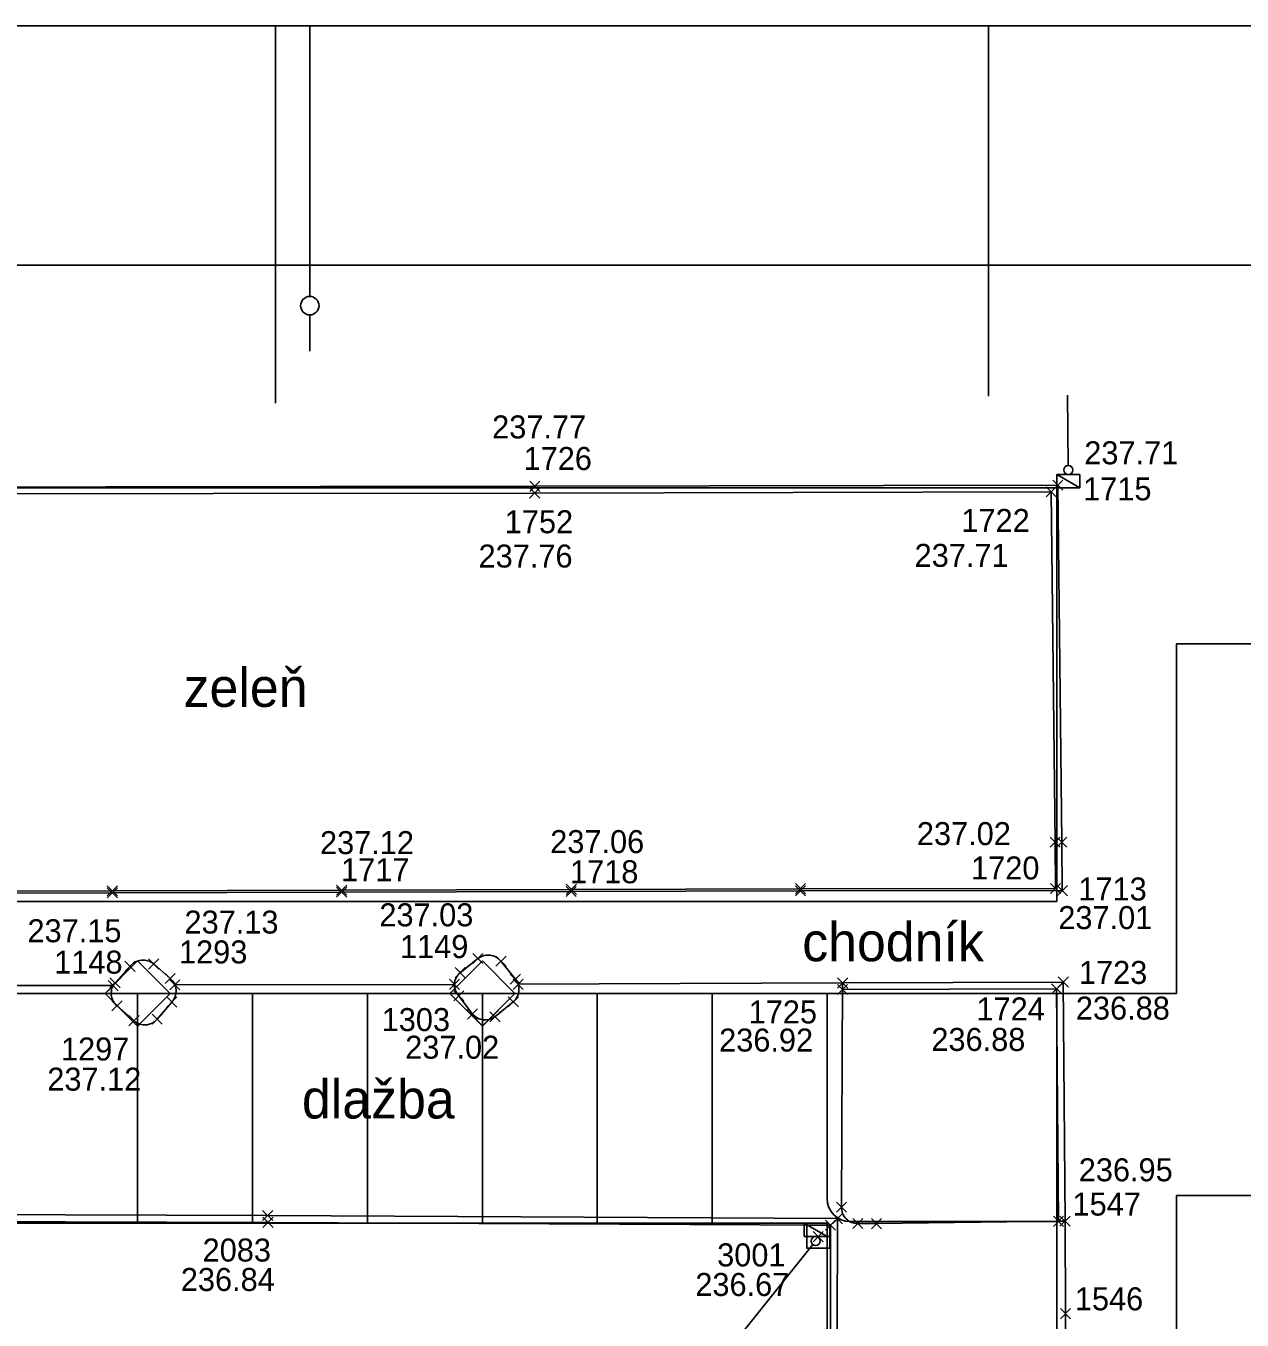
# Model space of a CAD drawing. Extents: x -264165 to -263733, y -1242319 to -1242245.
# Drawn here: x -263824.5 to -263798.04, y -1242273.09 to -1242244.94 of the extents above; entities that cross this region are included whole.
import ezdxf

# ---------------------------------------------------------------- set-up
doc = ezdxf.new("R2010")
doc.units = 0
for name, color, linetype in [('KFA_BOD_CISLO', 7, 'Continuous'), ('KFA_BOD_SYMBOL', 7, 'Continuous'), ('KFA_BOD_VYSKA', 7, 'Continuous'), ('KFA_SO_20-2_OBRUBNIKY_DOLNA_HRANA', 7, 'Continuous'), ('KFA_SO_20-2_OBRUBNIKY_HORNA_HRANA', 7, 'Continuous'), ('KFA_UV_BOD_CISLO', 7, 'Continuous'), ('KFA_UV_BOD_SYMBOL', 7, 'Continuous'), ('KFA_UV_BOD_VYSKA', 7, 'Continuous'), ('POPIS', 7, 'Continuous'), ('PROJEKT_OBRUBNIKY_KOMUNIKACIE', 7, 'Continuous'), ('PROJEKT_TDZ_VODOROVNE', 7, 'Continuous'), ('RAM_NA_TLAC_1-250', 7, 'Continuous'), ('SITUACIA_DSP_2D', 7, 'Continuous'), ('ULICNA_VPUST_POKLOP', 7, 'Continuous')]:
    doc.layers.add(name, color=color, linetype=linetype)

msp = doc.modelspace()

# ---------------------------------------------------------------- linework, layer by layer
at = {"layer": 'KFA_BOD_SYMBOL'}
for p, q in [((-263813.54, -1242255.208), (-263813.318, -1242254.988)), ((-263813.318, -1242255.208), (-263813.54, -1242254.988)), ((-263813.539, -1242255.062), (-263813.318, -1242254.84)), ((-263813.318, -1242255.062), (-263813.539, -1242254.84)), ((-263802.302, -1242255.184), (-263802.081, -1242254.964)), ((-263802.081, -1242255.184), (-263802.302, -1242254.964)), ((-263802.16, -1242255.036), (-263801.938, -1242254.816)), ((-263801.938, -1242255.036), (-263802.16, -1242254.816)), ((-263802.217, -1242262.803), (-263801.996, -1242262.583)), ((-263801.996, -1242262.803), (-263802.217, -1242262.583)), ((-263802.073, -1242262.803), (-263801.851, -1242262.583)), ((-263801.851, -1242262.803), (-263802.073, -1242262.583)), ((-263822.729, -1242263.865), (-263822.508, -1242263.644)), ((-263822.508, -1242263.865), (-263822.729, -1242263.644)), ((-263822.728, -1242263.906), (-263822.507, -1242263.684)), ((-263822.507, -1242263.906), (-263822.728, -1242263.684)), ((-263817.742, -1242263.849), (-263817.52, -1242263.627)), ((-263817.52, -1242263.849), (-263817.742, -1242263.627)), ((-263817.74, -1242263.894), (-263817.519, -1242263.674)), ((-263817.519, -1242263.894), (-263817.74, -1242263.674)), ((-263812.745, -1242263.877), (-263812.524, -1242263.657)), ((-263812.524, -1242263.877), (-263812.745, -1242263.657)), ((-263812.743, -1242263.832), (-263812.522, -1242263.61)), ((-263812.522, -1242263.832), (-263812.743, -1242263.61)), ((-263807.758, -1242263.818), (-263807.536, -1242263.596)), ((-263807.536, -1242263.818), (-263807.758, -1242263.596)), ((-263807.756, -1242263.865), (-263807.535, -1242263.644)), ((-263807.535, -1242263.865), (-263807.756, -1242263.644)), ((-263802.209, -1242263.812), (-263801.987, -1242263.592)), ((-263801.987, -1242263.812), (-263802.209, -1242263.592)), ((-263802.062, -1242263.859), (-263801.841, -1242263.637)), ((-263801.841, -1242263.859), (-263802.062, -1242263.637)), ((-263814.777, -1242265.336), (-263814.556, -1242265.115)), ((-263814.556, -1242265.336), (-263814.777, -1242265.115)), ((-263814.274, -1242265.393), (-263814.052, -1242265.171)), ((-263814.052, -1242265.393), (-263814.274, -1242265.171)), ((-263822.345, -1242265.505), (-263822.123, -1242265.285)), ((-263822.123, -1242265.505), (-263822.345, -1242265.285)), ((-263821.829, -1242265.454), (-263821.608, -1242265.232)), ((-263821.608, -1242265.454), (-263821.829, -1242265.232)), ((-263815.163, -1242265.646), (-263814.942, -1242265.424)), ((-263814.942, -1242265.646), (-263815.163, -1242265.424)), ((-263822.71, -1242265.926), (-263822.489, -1242265.704)), ((-263822.489, -1242265.926), (-263822.71, -1242265.704)), ((-263822.67, -1242265.866), (-263822.448, -1242265.644)), ((-263822.448, -1242265.866), (-263822.67, -1242265.644)), ((-263821.47, -1242265.772), (-263821.25, -1242265.552)), ((-263821.25, -1242265.772), (-263821.47, -1242265.552)), ((-263821.368, -1242265.91), (-263821.147, -1242265.69)), ((-263821.147, -1242265.91), (-263821.368, -1242265.69)), ((-263815.285, -1242265.897), (-263815.064, -1242265.677)), ((-263815.064, -1242265.897), (-263815.285, -1242265.677)), ((-263813.96, -1242265.786), (-263813.739, -1242265.566)), ((-263813.739, -1242265.786), (-263813.96, -1242265.566)), ((-263813.9, -1242265.896), (-263813.679, -1242265.674)), ((-263813.679, -1242265.896), (-263813.9, -1242265.674)), ((-263806.84, -1242265.867), (-263806.619, -1242265.646)), ((-263806.619, -1242265.867), (-263806.84, -1242265.646)), ((-263802.041, -1242265.847), (-263801.819, -1242265.627)), ((-263801.819, -1242265.847), (-263802.041, -1242265.627)), ((-263815.191, -1242266.149), (-263814.97, -1242265.927)), ((-263814.97, -1242266.149), (-263815.191, -1242265.927)), ((-263806.842, -1242266.009), (-263806.621, -1242265.789)), ((-263806.621, -1242266.009), (-263806.842, -1242265.789)), ((-263802.185, -1242265.995), (-263801.964, -1242265.775)), ((-263801.964, -1242265.995), (-263802.185, -1242265.775)), ((-263822.627, -1242266.363), (-263822.405, -1242266.143)), ((-263822.405, -1242266.363), (-263822.627, -1242266.143)), ((-263821.433, -1242266.284), (-263821.212, -1242266.062)), ((-263821.212, -1242266.284), (-263821.433, -1242266.062)), ((-263814.007, -1242266.279), (-263813.785, -1242266.059)), ((-263813.785, -1242266.279), (-263814.007, -1242266.059)), ((-263822.258, -1242266.69), (-263822.036, -1242266.468)), ((-263822.036, -1242266.69), (-263822.258, -1242266.468)), ((-263821.754, -1242266.654), (-263821.533, -1242266.434)), ((-263821.533, -1242266.654), (-263821.754, -1242266.434)), ((-263814.894, -1242266.543), (-263814.672, -1242266.323)), ((-263814.672, -1242266.543), (-263814.894, -1242266.323)), ((-263814.405, -1242266.603), (-263814.183, -1242266.382)), ((-263814.183, -1242266.603), (-263814.405, -1242266.382)), ((-263806.866, -1242270.747), (-263806.644, -1242270.525)), ((-263806.644, -1242270.747), (-263806.866, -1242270.525)), ((-263819.35, -1242270.927), (-263819.128, -1242270.707)), ((-263819.128, -1242270.927), (-263819.35, -1242270.707)), ((-263806.951, -1242270.995), (-263806.73, -1242270.774)), ((-263806.73, -1242270.995), (-263806.951, -1242270.774)), ((-263819.344, -1242271.076), (-263819.122, -1242270.855)), ((-263819.122, -1242271.076), (-263819.344, -1242270.855)), ((-263807.105, -1242271.137), (-263806.883, -1242270.916)), ((-263806.883, -1242271.137), (-263807.105, -1242270.916)), ((-263806.508, -1242271.1), (-263806.287, -1242270.88)), ((-263806.287, -1242271.1), (-263806.508, -1242270.88)), ((-263806.105, -1242271.103), (-263805.883, -1242270.883)), ((-263805.883, -1242271.103), (-263806.105, -1242270.883)), ((-263802.145, -1242271.052), (-263801.924, -1242270.832)), ((-263801.924, -1242271.052), (-263802.145, -1242270.832)), ((-263802.001, -1242271.049), (-263801.78, -1242270.829)), ((-263801.78, -1242271.049), (-263802.001, -1242270.829)), ((-263801.992, -1242273.062), (-263801.771, -1242272.84)), ((-263801.771, -1242273.062), (-263801.992, -1242272.84))]:
    msp.add_line(p, q, dxfattribs=at)
at = {"layer": 'KFA_SO_20-2_OBRUBNIKY_DOLNA_HRANA'}
for p, q in [((-263819.239, -1242270.817), (-263806.84, -1242270.884)), ((-263819.233, -1242270.965), (-263806.994, -1242271.026))]:
    msp.add_line(p, q, dxfattribs=at)
for points in [[(-263870.268, -1242270.778), (-263860.244, -1242270.766), (-263850.281, -1242270.766), (-263840.271, -1242270.772), (-263830.256, -1242270.782), (-263819.239, -1242270.817)], [(-263870.27, -1242270.923), (-263860.247, -1242270.914), (-263850.285, -1242270.903), (-263840.274, -1242270.913), (-263830.254, -1242270.929), (-263819.233, -1242270.965)], [(-263806.994, -1242271.026), (-263807.002, -1242275.743), (-263807.011, -1242281.745), (-263807.02, -1242285.741), (-263807.029, -1242285.754), (-263811.073, -1242288.555), (-263815.133, -1242291.369), (-263816.759, -1242292.501), (-263817.492, -1242292.982)], [(-263806.84, -1242270.884), (-263806.855, -1242275.745), (-263806.866, -1242281.754), (-263806.878, -1242285.825), (-263810.985, -1242288.673), (-263815.032, -1242291.478), (-263816.678, -1242292.619), (-263817.431, -1242293.129)]]:
    msp.add_lwpolyline(points, dxfattribs=at)
at = {"layer": 'KFA_SO_20-2_OBRUBNIKY_HORNA_HRANA'}
for p, q in [((-263801.962, -1242262.693), (-263802.049, -1242254.926)), ((-263802.106, -1242262.693), (-263802.192, -1242255.074)), ((-263802.098, -1242263.702), (-263802.106, -1242262.693)), ((-263801.952, -1242263.748), (-263801.962, -1242262.693)), ((-263826.616, -1242263.765), (-263822.618, -1242263.754)), ((-263822.618, -1242263.754), (-263817.631, -1242263.738)), ((-263817.631, -1242263.738), (-263812.633, -1242263.721)), ((-263817.629, -1242263.784), (-263812.634, -1242263.767)), ((-263812.634, -1242263.767), (-263807.645, -1242263.754)), ((-263812.633, -1242263.721), (-263807.647, -1242263.707)), ((-263807.647, -1242263.707), (-263802.098, -1242263.702)), ((-263807.645, -1242263.754), (-263801.952, -1242263.748)), ((-263826.618, -1242263.814), (-263822.617, -1242263.795)), ((-263822.617, -1242263.795), (-263817.629, -1242263.784)), ((-263822.559, -1242265.755), (-263822.234, -1242265.395)), ((-263821.719, -1242265.343), (-263821.36, -1242265.662)), ((-263814.666, -1242265.225), (-263815.052, -1242265.535)), ((-263814.163, -1242265.282), (-263813.85, -1242265.676)), ((-263801.93, -1242265.737), (-263806.73, -1242265.756)), ((-263801.93, -1242265.737), (-263801.89, -1242270.939)), ((-263822.6, -1242265.815), (-263828.894, -1242265.814)), ((-263815.175, -1242265.787), (-263821.258, -1242265.8)), ((-263806.73, -1242265.756), (-263813.79, -1242265.785)), ((-263806.755, -1242270.636), (-263806.73, -1242265.756)), ((-263802.074, -1242265.885), (-263806.731, -1242265.899)), ((-263802.035, -1242270.942), (-263802.074, -1242265.885)), ((-263822.147, -1242266.579), (-263822.516, -1242266.253)), ((-263821.323, -1242266.173), (-263821.644, -1242266.544)), ((-263814.783, -1242266.433), (-263815.08, -1242266.038)), ((-263813.896, -1242266.169), (-263814.294, -1242266.492))]:
    msp.add_line(p, q, dxfattribs=at)
for points in [[(-263802.049, -1242254.926), (-263813.428, -1242254.951), (-263827.432, -1242254.972), (-263838.432, -1242254.983), (-263849.438, -1242255.005), (-263849.439, -1242255.15), (-263841.634, -1242259.614), (-263834.328, -1242263.776)], [(-263802.192, -1242255.074), (-263813.429, -1242255.098), (-263827.439, -1242255.117), (-263838.432, -1242255.13), (-263849.367, -1242255.152), (-263841.614, -1242259.571), (-263834.235, -1242263.776)], [(-263806.349, -1242285.768), (-263802.019, -1242285.94), (-263801.893, -1242285.938), (-263801.891, -1242280.951), (-263801.886, -1242277.952), (-263801.882, -1242272.951), (-263801.89, -1242270.939), (-263802.035, -1242270.942), (-263805.994, -1242270.993), (-263806.398, -1242270.99)]]:
    msp.add_lwpolyline(points, dxfattribs=at)
for centre, major_axis, ratio, start_param, end_param in [((-263814.444, -1242265.51), (-0.294, -0.211), 0.999476, 3.200491, 4.751966), ((-263821.951, -1242265.62), (-0.167, -0.321), 0.9994, 2.924324, 4.51992), ((-263821.587, -1242265.935), (-0.331, 0.129), 0.999663, 2.781, 4.392907), ((-263814.83, -1242265.8), (-0.107, -0.329), 0.99892, 4.155279, 5.787915), ((-263814.125, -1242265.899), (0.104, 0.339), 0.999804, 4.144434, 5.691048), ((-263822.292, -1242265.983), (0.148, -0.318), 0.999983, 3.571683, 5.157294), ((-263821.912, -1242266.322), (0.101, 0.333), 0.999818, 2.695, 4.315083), ((-263814.508, -1242266.207), (0.332, -0.129), 0.999699, 4.199481, 5.726814), ((-263806.412, -1242270.646), (0.059, -0.339), 0.999408, 4.508665, 6.149259)]:
    msp.add_ellipse(centre, major_axis=major_axis, ratio=ratio, start_param=start_param, end_param=end_param, dxfattribs=at)
at = {"layer": 'KFA_UV_BOD_SYMBOL'}
for p, q in [((-263807.372, -1242271.386), (-263807.15, -1242271.164)), ((-263807.15, -1242271.386), (-263807.372, -1242271.164))]:
    msp.add_line(p, q, dxfattribs=at)
at = {"layer": 'PROJEKT_OBRUBNIKY_KOMUNIKACIE'}
for p, q in [((-263807.068, -1242265.987), (-263917.08, -1242265.983)), ((-263807.068, -1242270.447), (-263807.068, -1242265.987)), ((-263802.068, -1242270.24), (-263802.068, -1242265.987)), ((-263917.578, -1242270.983), (-263807.068, -1242270.982)), ((-263807.068, -1242270.982), (-263807.068, -1242285.823)), ((-263802.068, -1242270.947), (-263806.568, -1242270.947)), ((-263802.068, -1242280.24), (-263802.068, -1242271.654))]:
    msp.add_line(p, q, dxfattribs=at)
for points in [[(-263802.068, -1242263.988), (-263834.256, -1242263.984), (-263849.468, -1242254.985), (-263802.068, -1242254.987), (-263802.068, -1242263.988)], [(-263798.064, -1242282.882), (-263794.987, -1242278.383), (-263796.968, -1242278.382), (-263796.968, -1242274.382), (-263799.468, -1242274.382), (-263799.468, -1242270.382), (-263791.968, -1242270.382), (-263791.968, -1242266.382), (-263796.968, -1242266.382), (-263796.968, -1242260.382), (-263791.968, -1242260.382), (-263791.968, -1242258.382), (-263799.468, -1242258.382), (-263799.468, -1242265.987), (-263802.068, -1242265.987)], [(-263822.068, -1242265.279), (-263821.361, -1242265.986), (-263822.068, -1242266.694), (-263822.775, -1242265.986), (-263822.068, -1242265.279)], [(-263814.568, -1242265.279), (-263813.861, -1242265.986), (-263814.568, -1242266.694), (-263815.275, -1242265.986), (-263814.568, -1242265.279)], [(-263802.068, -1242265.987), (-263802.068, -1242270.24), (-263802.068, -1242270.947), (-263802.068, -1242271.654), (-263802.068, -1242273.447), (-263802.068, -1242275.947), (-263802.068, -1242278.447), (-263802.068, -1242280.24), (-263802.068, -1242281.654), (-263802.068, -1242283.447), (-263802.068, -1242285.947), (-263806.656, -1242285.943)]]:
    msp.add_lwpolyline(points, dxfattribs=at)
msp.add_arc((-263806.568, -1242270.447), 0.5, 180, 270, dxfattribs=at)
at = {"layer": 'PROJEKT_TDZ_VODOROVNE'}
for p, q in [((-263822.068, -1242270.982), (-263822.068, -1242265.982)), ((-263819.568, -1242270.982), (-263819.568, -1242265.982)), ((-263817.068, -1242270.982), (-263817.068, -1242265.982)), ((-263814.568, -1242270.982), (-263814.568, -1242265.982)), ((-263812.068, -1242270.982), (-263812.068, -1242265.982)), ((-263809.568, -1242270.982), (-263809.568, -1242265.982))]:
    msp.add_line(p, q, dxfattribs=at)
at = {"layer": 'RAM_NA_TLAC_1-250'}
msp.add_lwpolyline([(-264165.363, -1242244.935), (-263732.863, -1242244.935), (-263732.863, -1242319.185), (-264165.363, -1242319.185)], close=True, dxfattribs=at)
at = {"layer": 'SITUACIA_DSP_2D'}
for p, q in [((-263819.068, -1242244.935), (-263819.068, -1242253.146)), ((-263818.32, -1242244.935), (-263818.321, -1242250.822)), ((-263803.556, -1242244.935), (-263803.556, -1242252.989)), ((-263924.143, -1242250.14), (-263788.143, -1242250.14)), ((-263818.322, -1242251.222), (-263818.322, -1242252.009)), ((-263801.822, -1242254.497), (-263801.837, -1242252.972)), ((-263802.071, -1242254.697), (-263801.571, -1242254.697)), ((-263802.071, -1242254.987), (-263802.071, -1242254.697)), ((-263802.071, -1242254.697), (-263801.571, -1242254.987)), ((-263802.071, -1242254.697), (-263801.571, -1242254.987)), ((-263801.571, -1242254.697), (-263802.071, -1242254.697)), ((-263801.571, -1242254.697), (-263801.571, -1242254.987)), ((-263801.571, -1242254.987), (-263801.571, -1242254.697)), ((-263801.571, -1242254.987), (-263802.071, -1242254.987)), ((-263807.068, -1242270.447), (-263807.068, -1242265.987)), ((-263807.068, -1242265.987), (-263802.068, -1242265.987)), ((-263802.068, -1242270.24), (-263802.068, -1242265.987)), ((-263807.568, -1242270.982), (-263807.068, -1242270.982)), ((-263807.568, -1242271.272), (-263807.568, -1242270.982)), ((-263807.568, -1242270.982), (-263807.068, -1242271.272)), ((-263807.568, -1242270.982), (-263807.068, -1242271.272)), ((-263807.068, -1242270.982), (-263807.568, -1242270.982)), ((-263807.068, -1242270.982), (-263807.068, -1242271.272)), ((-263807.068, -1242271.272), (-263807.068, -1242270.982)), ((-263802.068, -1242270.947), (-263806.568, -1242270.947)), ((-263807.068, -1242271.272), (-263807.568, -1242271.272)), ((-263807.38, -1242271.45), (-263817.128, -1242283.593)), ((-263802.068, -1242280.24), (-263802.068, -1242271.654))]:
    msp.add_line(p, q, dxfattribs=at)
for points in [[(-263802.068, -1242263.988), (-263834.256, -1242263.984), (-263849.468, -1242254.985), (-263802.068, -1242254.987)], [(-263822.068, -1242265.279), (-263821.361, -1242265.986), (-263822.068, -1242266.694), (-263822.775, -1242265.986)], [(-263814.568, -1242265.279), (-263813.861, -1242265.986), (-263814.568, -1242266.693), (-263815.275, -1242265.986)]]:
    msp.add_lwpolyline(points, close=True, dxfattribs=at)
for points in [[(-263798.064, -1242282.882), (-263794.987, -1242278.383), (-263796.968, -1242278.382), (-263796.968, -1242274.382), (-263799.468, -1242274.382), (-263799.468, -1242270.382), (-263791.968, -1242270.382), (-263791.968, -1242266.382), (-263796.968, -1242266.382), (-263796.968, -1242260.382), (-263791.968, -1242260.382), (-263791.968, -1242258.382), (-263799.468, -1242258.382), (-263799.468, -1242265.987), (-263802.068, -1242265.987)], [(-263802.068, -1242265.987), (-263802.068, -1242270.24), (-263802.068, -1242270.947), (-263802.068, -1242271.654), (-263802.068, -1242273.447), (-263802.068, -1242275.947), (-263802.068, -1242278.447), (-263802.068, -1242280.24), (-263802.068, -1242280.24), (-263802.068, -1242281.654), (-263802.068, -1242283.447), (-263802.068, -1242285.947), (-263806.656, -1242285.943)]]:
    msp.add_lwpolyline(points, dxfattribs=at)
for centre, radius in [((-263818.322, -1242251.022), 0.2), ((-263801.821, -1242254.597), 0.1), ((-263807.318, -1242271.372), 0.1)]:
    msp.add_circle(centre, radius, dxfattribs=at)
msp.add_arc((-263806.568, -1242270.447), 0.5, 180, 270, dxfattribs=at)
at = {"layer": 'ULICNA_VPUST_POKLOP'}
msp.add_line((-263807.261, -1242271.275), (-263807.261, -1242271.275), dxfattribs=at)
msp.add_lwpolyline([(-263807.511, -1242271.275), (-263807.511, -1242271.025), (-263807.011, -1242271.025), (-263807.011, -1242271.525), (-263807.511, -1242271.525), (-263807.511, -1242271.275), (-263807.011, -1242271.275)], dxfattribs=at)

# ---------------------------------------------------------------- texts
at = {"layer": 'KFA_BOD_CISLO'}
for s, p in [('1726', (-263813.672, -1242254.597)), ('1715', (-263801.497, -1242255.257)), ('1752', (-263814.081, -1242255.973)), ('1722', (-263804.147, -1242255.945)), ('1717', (-263817.642, -1242263.543)), ('1718', (-263812.661, -1242263.587)), ('1720', (-263803.935, -1242263.505)), ('1713', (-263801.602, -1242263.962)), ('1293', (-263821.169, -1242265.332)), ('1149', (-263816.36, -1242265.215)), ('1148', (-263823.884, -1242265.554)), ('1723', (-263801.59, -1242265.778)), ('1303', (-263816.759, -1242266.804)), ('1725', (-263808.775, -1242266.638)), ('1724', (-263803.818, -1242266.572)), ('1297', (-263823.736, -1242267.444)), ('1547', (-263801.729, -1242270.818)), ('2083', (-263820.655, -1242271.818)), ('1546', (-263801.678, -1242272.879))]:
    msp.add_text(s, height=0.5, dxfattribs=at).set_placement(p)
at = {"layer": 'KFA_BOD_VYSKA'}
for s, p in [('237.77', (-263814.356, -1242253.91)), ('237.71', (-263801.473, -1242254.473)), ('237.76', (-263814.651, -1242256.719)), ('237.71', (-263805.164, -1242256.704)), ('237.02', (-263805.115, -1242262.758)), ('237.12', (-263818.101, -1242262.954)), ('237.06', (-263813.092, -1242262.932)), ('237.03', (-263816.809, -1242264.525)), ('237.13', (-263821.049, -1242264.682)), ('237.01', (-263802.038, -1242264.585)), ('237.15', (-263824.465, -1242264.871)), ('236.88', (-263801.656, -1242266.554)), ('236.92', (-263809.417, -1242267.249)), ('236.88', (-263804.8, -1242267.236)), ('237.02', (-263816.247, -1242267.405)), ('237.12', (-263824.034, -1242268.1)), ('236.95', (-263801.593, -1242270.072)), ('236.84', (-263821.129, -1242272.458))]:
    msp.add_text(s, height=0.5, dxfattribs=at).set_placement(p)
at = {"layer": 'KFA_UV_BOD_CISLO'}
msp.add_text('3001', height=0.5, dxfattribs=at).set_placement((-263809.46, -1242271.923))
at = {"layer": 'KFA_UV_BOD_VYSKA'}
msp.add_text('236.67', height=0.5, dxfattribs=at).set_placement((-263809.935, -1242272.567))
at = {"layer": 'POPIS'}
for s, p in [('zeleň', (-263821.069, -1242259.75)), ('chodník', (-263807.61, -1242265.285)), ('dlažba', (-263818.494, -1242268.705))]:
    msp.add_text(s, height=0.8438, dxfattribs=at).set_placement(p)

doc.saveas('drawing.dxf')
